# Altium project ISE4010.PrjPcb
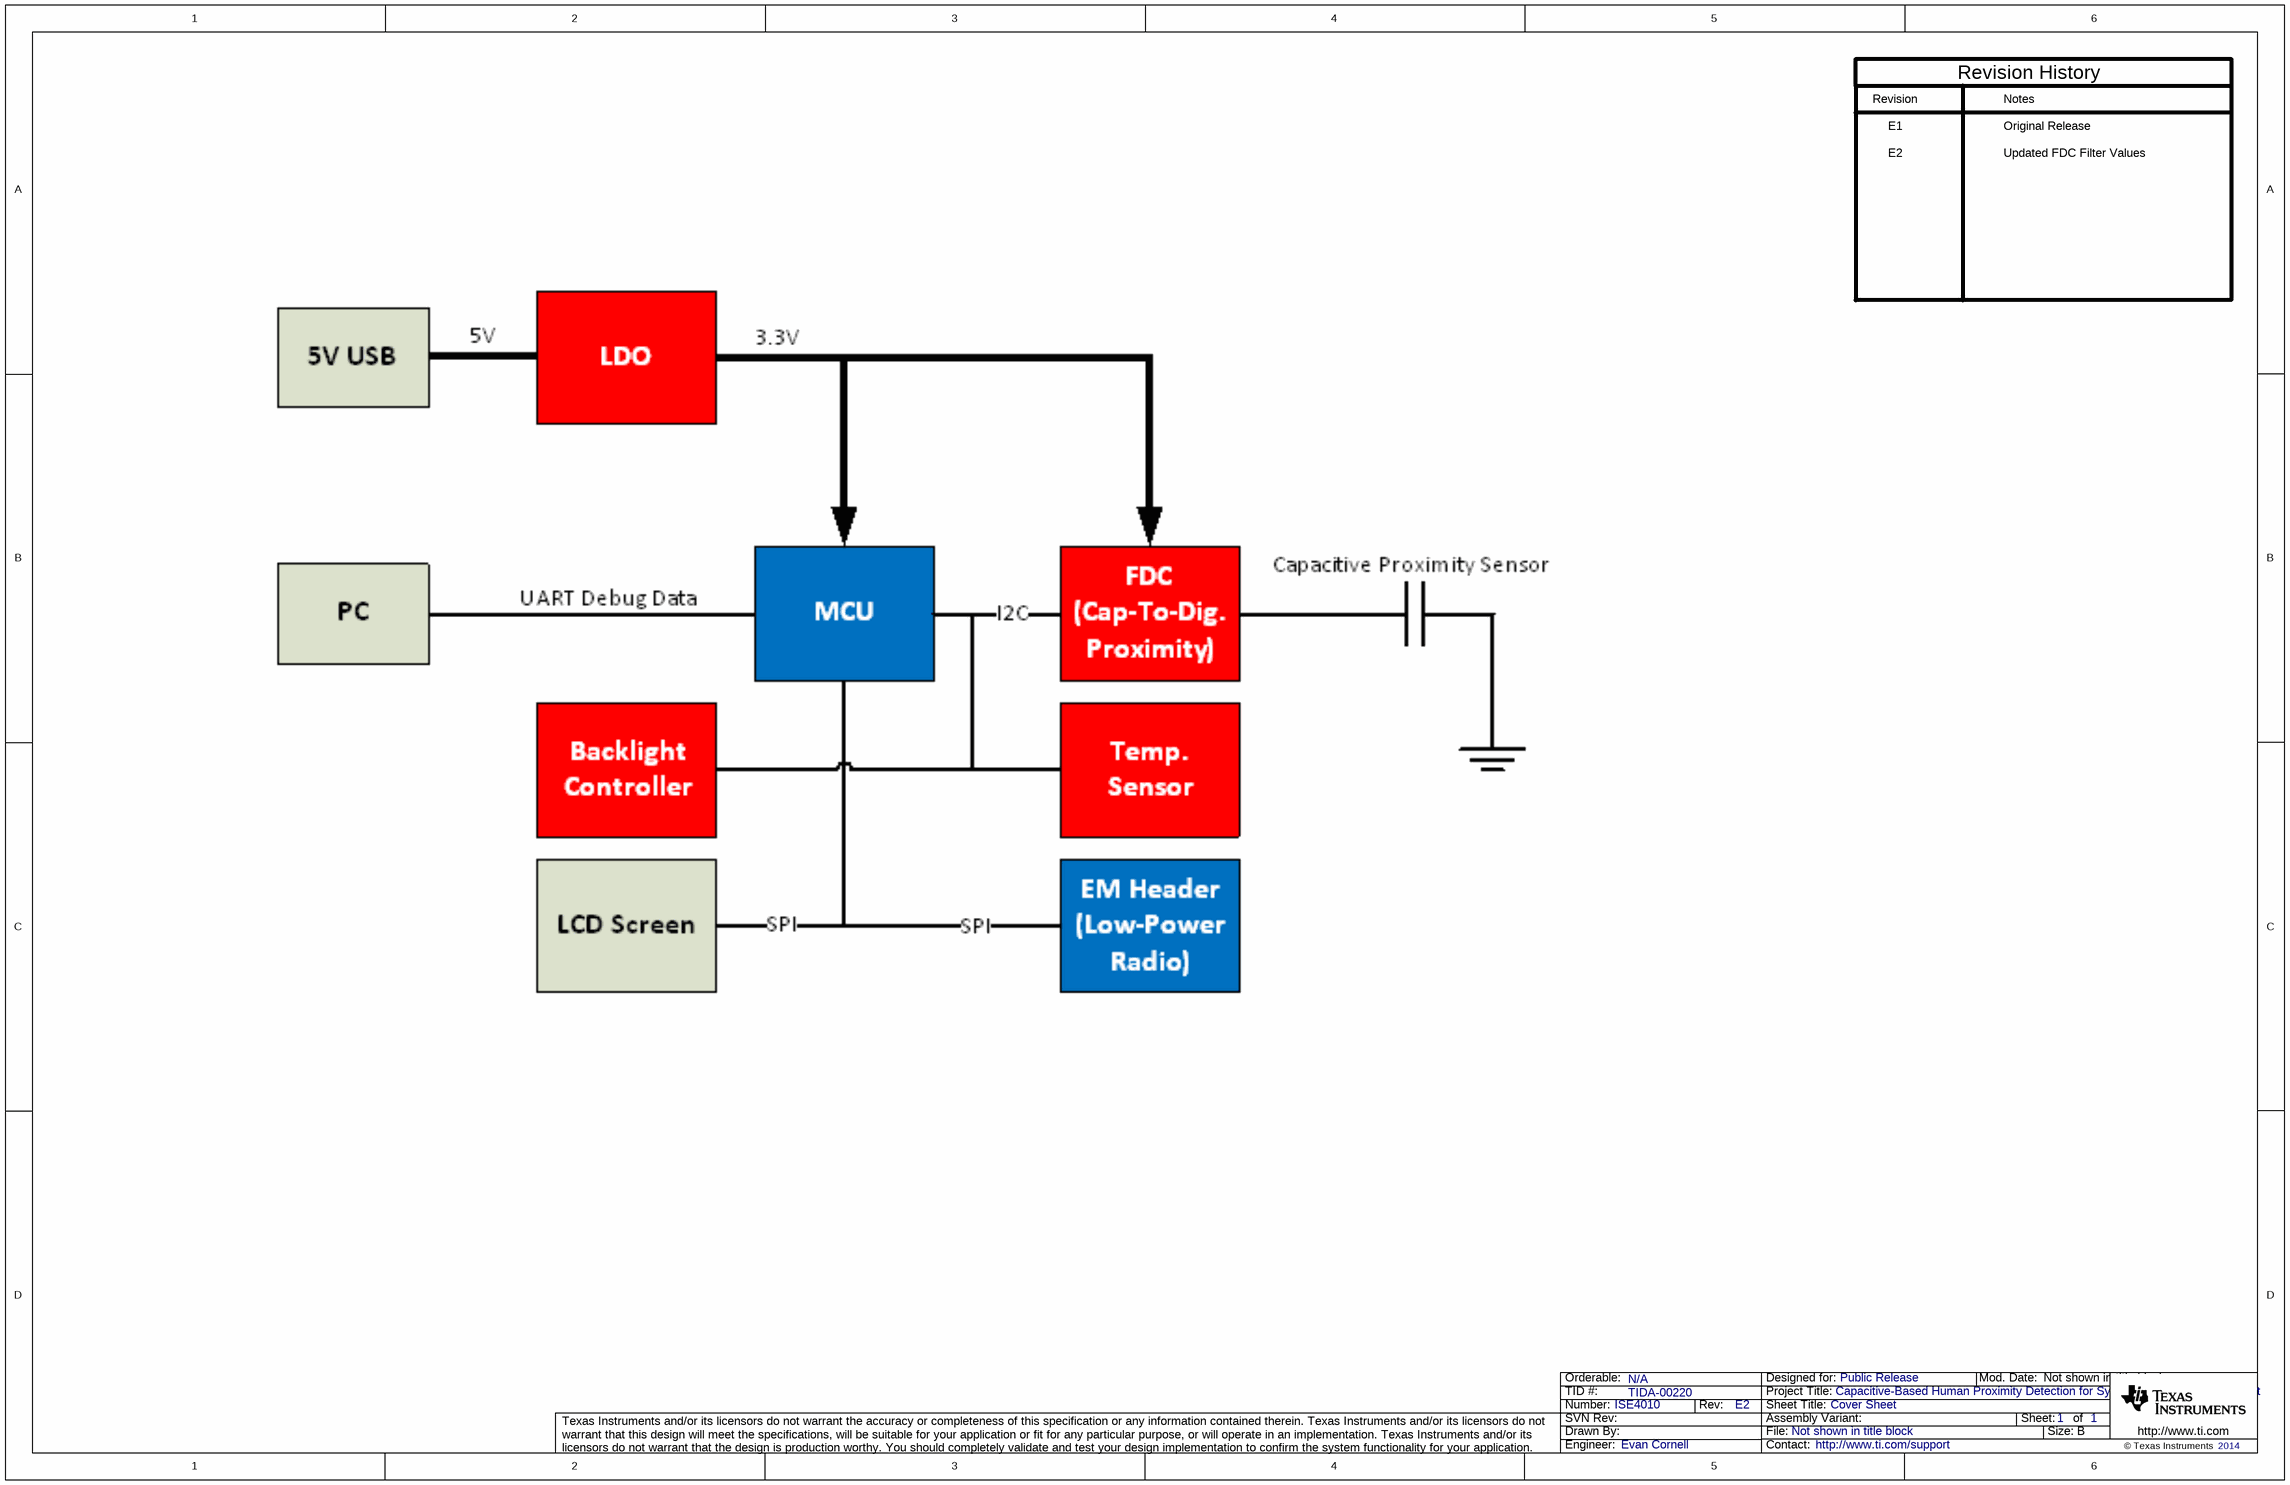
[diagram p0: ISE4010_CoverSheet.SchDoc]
CopyrightYear: 2014; EVM_orderable: N/A; PCB_Layout: Krypton Solutions /JM; PCB_Rev: E2; PRJ_Customer: Public Release; PRJ_Engineer: Evan Cornell; PRJ_Number: ISE4010; PRJ_Title: Capacitive-Based Human Proximity Detection for System Wake-Up and Interrupt; SCH_Rev: E2; TechSupport: http://www.ti.com/support; TID: TIDA-00220
4 sheets, 162 parts. Net scope: global (net labels, ports and power ports of the same name join across sheets).
Board file: ISE4010_TID.PcbDoc
Sheets:
  ISE4010_CoverSheet.SchDoc
  ISE4010_MSP430.SchDoc
  ISE4010_FDC_LCD.SchDoc
  ISE4010_TID_Hardware.SchDoc

## Sheet ISE4010_CoverSheet.SchDoc: Cover Sheet
size 431 x 279 mm; Date: Not shown in title block; ApprovedBy: Not shown in title block; CheckedBy: Not shown in title block; Author: Not shown in title block; CompanyName: Not shown in title block; Engineer: Not shown in title block; Organization: Not shown in title block; Address1: Not shown in title block; Address2: Not shown in title block; Address3: Not shown in title block; Address4: Not shown in title block; DocumentNumber: 1; Revision: Use project parameter SCH_Rev; SheetNumber: 1; SheetTotal: 1; PageSetup: Record=PageOptions¦CenterHorizontal=True¦CenterVertical=True¦PrintScale=1.00¦XCorrection=1.00¦YCorrection=1.00¦PrintKind=0¦BorderSize=5000000¦LeftOffset=0¦BottomOffset=0¦Orientation=2¦PaperLength=1000¦PaperWidth=1000¦Scale=100¦PaperSource=15¦PrintQuality=600¦MediaType=1¦DitherType=10¦PaperKind=Letter¦PrintScaleMode=1

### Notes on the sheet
- Revision
- Notes
- Revision History
- E1
- E2
- Original Release
- Updated FDC Filter Values

## Sheet ISE4010_MSP430.SchDoc: MSP430
size 431 x 279 mm; Date: Not shown in title block; ApprovedBy: Not shown in title block; CheckedBy: Not shown in title block; Author: Not shown in title block; CompanyName: Not shown in title block; DrawnBy: Evan Cornell; Engineer: Not shown in title block; Organization: Not shown in title block; Address1: Not shown in title block; Address2: Not shown in title block; Address3: Not shown in title block; Address4: Not shown in title block; DocumentNumber: 2; Revision: Use project parameter SCH_Rev; SheetNumber: 2; SheetTotal: 4; PageSetup: Record=PageOptions¦CenterHorizontal=True¦CenterVertical=True¦PrintScale=0.62¦XCorrection=1.00¦YCorrection=1.00¦PrintKind=0¦BorderSize=5000000¦LeftOffset=0¦BottomOffset=0¦Orientation=2¦PaperLength=1000¦PaperWidth=1000¦Scale=100¦PaperSource=15¦PrintQuality=600¦MediaType=1¦DitherType=10¦PaperKind=Letter¦PrintScaleMode=1
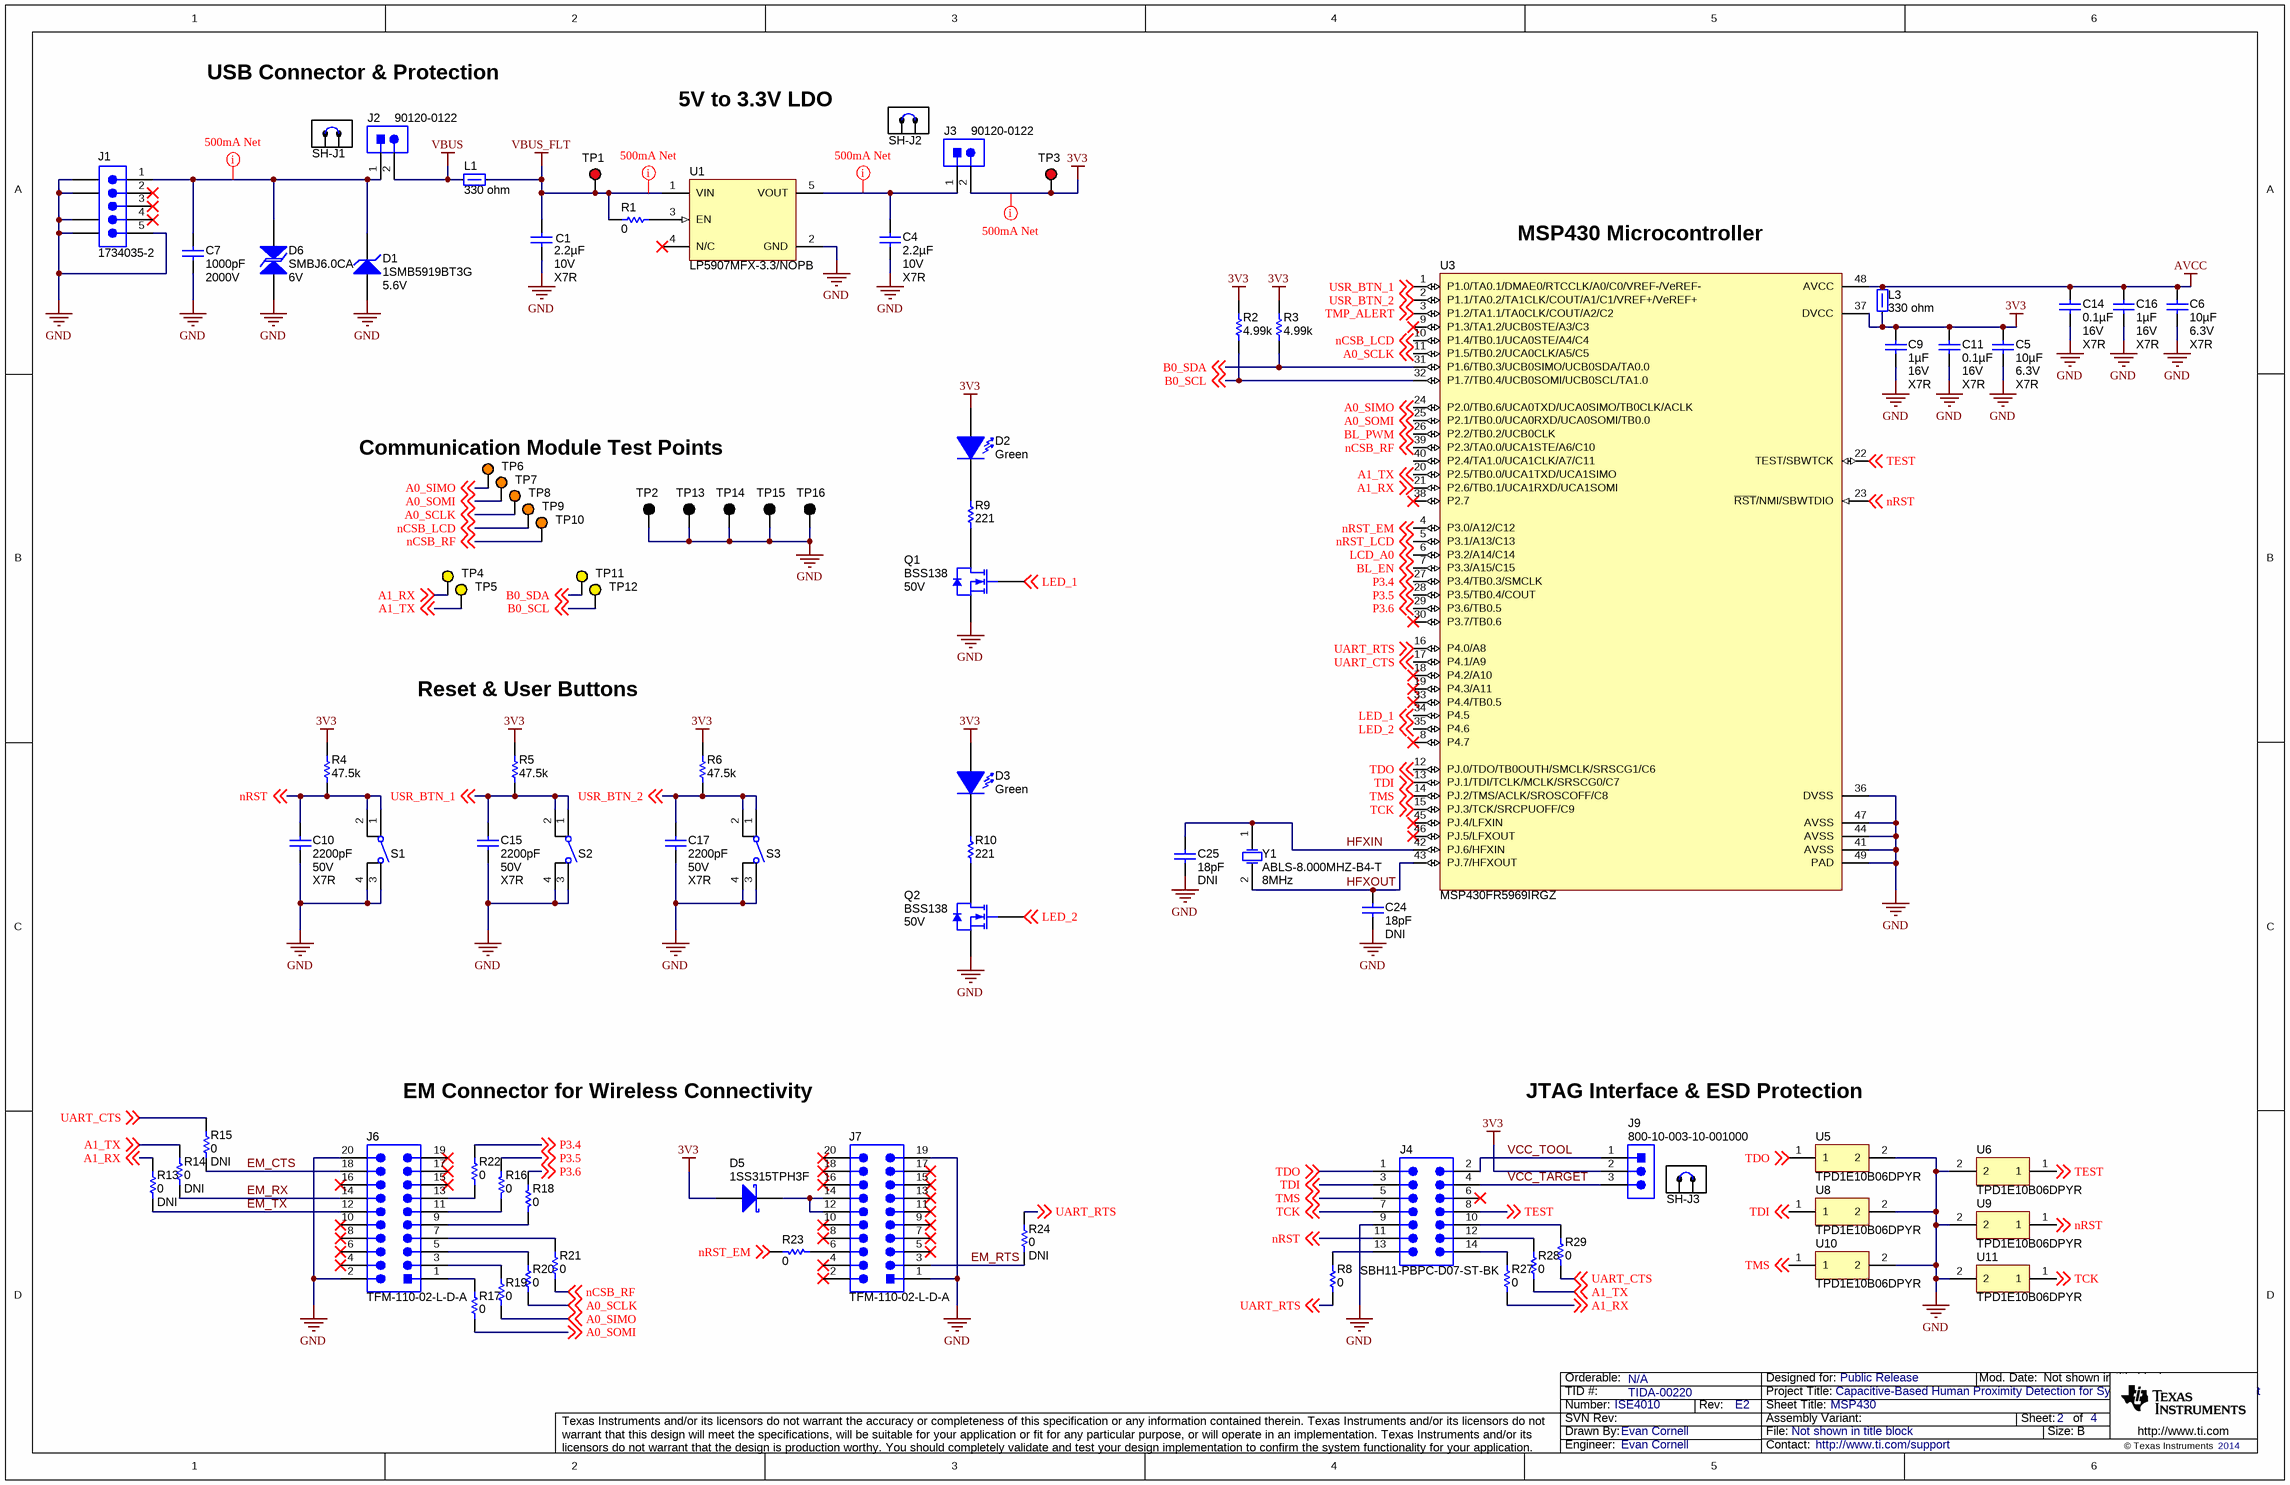
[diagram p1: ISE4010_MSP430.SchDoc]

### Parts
C1  ValueDisplayed: 2.2µF  Value2: 10V  TempCo: X7R  [0603]  (hidden comment: GRM188R71A225KE15D)
C4  ValueDisplayed: 2.2µF  Value2: 10V  TempCo: X7R  [0603]  (hidden comment: GRM188R71A225KE15D)
C5  ValueDisplayed: 10µF  Value2: 6.3V  TempCo: X7R  [0805_HV]  (hidden comment: C2012X7R0J106M125AB)
C6  ValueDisplayed: 10µF  Value2: 6.3V  TempCo: X7R  [0805_HV]  (hidden comment: C2012X7R0J106M125AB)
C7  ValueDisplayed: 1000pF  Value2: 2000V  [1210]  (hidden comment: C1210C102KGRACTU)
C9  ValueDisplayed: 1µF  Value2: 16V  TempCo: X7R  [0603]  (hidden comment: C1608X7R1C105K)
C10  ValueDisplayed: 2200pF  Value2: 50V  TempCo: X7R  [0402]  (hidden comment: C1005X7R1H222K)
C11  ValueDisplayed: 0.1µF  Value2: 16V  TempCo: X7R  [0402]  (hidden comment: GRM155R71C104KA88D)
C14  ValueDisplayed: 0.1µF  Value2: 16V  TempCo: X7R  [0402]  (hidden comment: GRM155R71C104KA88D)
C15  ValueDisplayed: 2200pF  Value2: 50V  TempCo: X7R  [0402]  (hidden comment: C1005X7R1H222K)
C16  ValueDisplayed: 1µF  Value2: 16V  TempCo: X7R  [0603]  (hidden comment: C1608X7R1C105K)
C17  ValueDisplayed: 2200pF  Value2: 50V  TempCo: X7R  [0402]  (hidden comment: C1005X7R1H222K)
C24  ValueDisplayed: 18pF  [0603]  (hidden comment: GRM1885C2A180JA01D)
C25  ValueDisplayed: 18pF  [0603]  (hidden comment: GRM1885C2A180JA01D)
D1  1SMB5919BT3G  value 5.6V  [SMB]
D2  value Green  [SML-P1_GREEN]  (hidden comment: SML-P12PTT86)
D3  value Green  [SML-P1_GREEN]  (hidden comment: SML-P12PTT86)
D5  1SS315TPH3F  [sod-323]
D6  SMBJ6.0CA  value 6V  [SMB]
J1  1734035-2  [CONN_USB-Mini-B-1734035-2]
J2  90120-0122  [CONN_90120-0122]
J3  90120-0122  [CONN_90120-0122]
J4  SBH11-PBPC-D07-ST-BK  [CONN_SBH11-PBPC-D07-ST-BK]
J6  TFM-110-02-L-D-A  [Samtec_TFM-110-02-L-D-A]
J7  TFM-110-02-L-D-A  [Samtec_TFM-110-02-L-D-A]
J9  800-10-003-10-001000  [Mill-Max_800-10-003-10-001000]
L1  value 330 ohm  [0603]  (hidden comment: BLM18SG331TN1D)
L3  value 330 ohm  [0603]  (hidden comment: BLM18SG331TN1D)
Q1  BSS138  value 50V  [SOT-23]
Q2  BSS138  value 50V  [SOT-23]
R1  value 0  [0402]  (hidden comment: CRCW04020000Z0ED)
R2  value 4.99k  [0402]  (hidden comment: CRCW04024K99FKED)
R3  value 4.99k  [0402]  (hidden comment: CRCW04024K99FKED)
R4  value 47.5k  [0603]  (hidden comment: CRCW060347K5FKEA)
R5  value 47.5k  [0603]  (hidden comment: CRCW060347K5FKEA)
R6  value 47.5k  [0603]  (hidden comment: CRCW060347K5FKEA)
R8  value 0  [0402]  (hidden comment: CRCW04020000Z0ED)
R9  value 221  [0402]  (hidden comment: CRCW0402221RFKED)
R10  value 221  [0402]  (hidden comment: CRCW0402221RFKED)
R13  value 0  [0402]  (hidden comment: CRCW04020000Z0ED)
R14  value 0  [0402]  (hidden comment: CRCW04020000Z0ED)
R15  value 0  [0402]  (hidden comment: CRCW04020000Z0ED)
R16  value 0  [0402]  (hidden comment: CRCW04020000Z0ED)
R17  value 0  [0402]  (hidden comment: CRCW04020000Z0ED)
R18  value 0  [0402]  (hidden comment: CRCW04020000Z0ED)
R19  value 0  [0402]  (hidden comment: CRCW04020000Z0ED)
R20  value 0  [0402]  (hidden comment: CRCW04020000Z0ED)
R21  value 0  [0402]  (hidden comment: CRCW04020000Z0ED)
R22  value 0  [0402]  (hidden comment: CRCW04020000Z0ED)
R23  value 0  [0402]  (hidden comment: CRCW04020000Z0ED)
R24  value 0  [0402]  (hidden comment: CRCW04020000Z0ED)
R27  value 0  [0402]  (hidden comment: CRCW04020000Z0ED)
R28  value 0  [0402]  (hidden comment: CRCW04020000Z0ED)
R29  value 0  [0402]  (hidden comment: CRCW04020000Z0ED)
S1  4-1437565-1  [SW_FSM4JSMA]  (value not drawn)
S2  4-1437565-1  [SW_FSM4JSMA]  (value not drawn)
S3  4-1437565-1  [SW_FSM4JSMA]  (value not drawn)
SH-J1  2SN-BK-G  [2SN-BK-G]  (value not drawn)
SH-J2  2SN-BK-G  [2SN-BK-G]  (value not drawn)
SH-J3  881545-2  [TE_881545-2]  (value not drawn)  (mechanical)
TP1  5000  [Keystone5000]  (value not drawn)
TP2  5001  [Keystone5001]  (value not drawn)
TP3  5000  [Keystone5000]  (value not drawn)
TP4  5004  [Keystone5004]  (value not drawn)
TP5  5004  [Keystone5004]  (value not drawn)
TP6  5003  [Keystone5003]  (value not drawn)
TP7  5003  [Keystone5003]  (value not drawn)
TP8  5003  [Keystone5003]  (value not drawn)
TP9  5003  [Keystone5003]  (value not drawn)
TP10  5003  [Keystone5003]  (value not drawn)
TP11  5004  [Keystone5004]  (value not drawn)
TP12  5004  [Keystone5004]  (value not drawn)
TP13  5001  [Keystone5001]  (value not drawn)
TP14  5001  [Keystone5001]  (value not drawn)
TP15  5001  [Keystone5001]  (value not drawn)
TP16  5001  [Keystone5001]  (value not drawn)
U1  LP5907MFX-3.3/NOPB  [DBV0005A_N]
U3  MSP430FR5969IRGZ  [RGZ0048B]
U5  TPD1E10B06DPYR  [DPY0002A]
U6  TPD1E10B06DPYR  [DPY0002A]
U8  TPD1E10B06DPYR  [DPY0002A]
U9  TPD1E10B06DPYR  [DPY0002A]
U10  TPD1E10B06DPYR  [DPY0002A]
U11  TPD1E10B06DPYR  [DPY0002A]
Y1  ABLS-8.000MHZ-B4-T  Frequency: 8MHz  [XTAL_CSM-7X]

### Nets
3V3: C5.1 C9.2 C11.2 D2.2(A) D3.2(A) D5.2(A) J3.2 J9.2 L3.1 R2.2 R3.2 R4.2 R5.2 R6.2 TP3.1 U3.37(DVCC)
AVCC: C6.1 C14.2 C16.2 L3.2 U3.48(AVCC)
GND: C1.1 C4.1 C5.2 C6.2 C7.2 C9.1 C10.2 C11.1 C14.1 C15.2 C16.1 C17.2 C24.2 C25.2 D1.2(A) D6.1 J1.5 J1.6(GND) J1.7(GND) J1.8(GND) J1.9(GND) J4.9 J6.2 J6.20 J7.1 J7.19 Q1.2(S) Q2.2(S) S1.3 S1.4 S2.3 S2.4 S3.3 S3.4 TP2.1 TP13.1 TP14.1 TP15.1 TP16.1 U1.2(GND) U3.36(DVSS) U3.41(AVSS) U3.44(AVSS) U3.47(AVSS) U3.49(PAD) U5.2 U6.2 U8.2 U9.2 U10.2 U11.2
VBUS: J2.2 L1.1
VBUS_FLT: C1.2 L1.2 R1.2 TP1.1 U1.1(VIN)
A0_SCLK: R20.2 TP8.1 U3.11(P1.5/TB0.2/UCA0CLK/A5/C5) ; off-sheet A0_SCLK
A0_SIMO: R19.2 TP6.1 U3.24(P2.0/TB0.6/UCA0TXD/UCA0SIMO/TB0CLK/ACLK) ; off-sheet A0_SIMO
A0_SOMI: R17.1 TP7.1 U3.25(P2.1/TB0.0/UCA0RXD/UCA0SOMI/TB0.0) ; off-sheet A0_SOMI
A1_RX: R13.1 R27.1 TP4.1 U3.21(P2.6/TB0.1/UCA1RXD/UCA1SOMI) ; off-sheet A1_RX
A1_TX: R14.1 R28.1 TP5.1 U3.20(P2.5/TB0.0/UCA1TXD/UCA1SIMO) ; off-sheet A1_TX
B0_SCL: R2.1 TP12.1 U3.32(P1.7/TB0.4/UCB0SOMI/UCB0SCL/TA1.0) ; off-sheet B0_SCL
B0_SDA: R3.1 TP11.1 U3.31(P1.6/TB0.3/UCB0SIMO/UCB0SDA/TA0.0) ; off-sheet B0_SDA
BL_EN: U3.7(P3.3/A15/C15) ; off-sheet BL_EN
BL_PWM: U3.26(P2.2/TB0.2/UCB0CLK) ; off-sheet BL_PWM
EM_CTS: J6.18 R15.1
EM_RTS: J7.3 R24.2
EM_RX: J6.14 R14.2
EM_TX: J6.12 R13.2
HFXIN: C25.1 U3.42(PJ.6/HFXIN) Y1.1(OSC1)
HFXOUT: C24.1 U3.43(PJ.7/HFXOUT) Y1.2(OSC2)
LCD_A0: U3.6(P3.2/A14/C14) ; off-sheet LCD_A0
LED_1: Q1.1(G) U3.34(P4.5) ; off-sheet LED_1
LED_2: Q2.1(G) U3.35(P4.6) ; off-sheet LED_2
nCSB_LCD: TP9.1 U3.10(P1.4/TB0.1/UCA0STE/A4/C4) ; off-sheet nCSB_LCD
nCSB_RF: R21.2 TP10.1 U3.39(P2.3/TA0.0/UCA1STE/A6/C10) ; off-sheet nCSB_RF
nRST: C10.1 J4.11 R4.1 S1.1 S1.2 U3.23(~{RST}/NMI/SBWTDIO) U9.1 ; off-sheet nRST
nRST_EM: R23.2 U3.4(P3.0/A12/C12) ; off-sheet nRST_EM
nRST_LCD: U3.5(P3.1/A13/C13) ; off-sheet nRST_LCD
P3.4: R22.2 U3.27(P3.4/TB0.3/SMCLK) ; off-sheet P3.4
P3.5: R16.1 U3.28(P3.5/TB0.4/COUT) ; off-sheet P3.5
P3.6: R18.1 U3.29(P3.6/TB0.5) ; off-sheet P3.6
TCK: J4.7 U3.15(PJ.3/TCK/SRCPUOFF/C9) U11.1 ; off-sheet TCK
TDI: J4.3 U3.13(PJ.1/TDI/TCLK/MCLK/SRSCG0/C7) U8.1 ; off-sheet TDI
TDO: J4.1 U3.12(PJ.0/TDO/TB0OUTH/SMCLK/SRSCG1/C6) U5.1 ; off-sheet TDO
TEST: J4.8 U3.22(TEST/SBWTCK) U6.1 ; off-sheet TEST
TMP_ALERT: U3.3(P1.2/TA1.1/TA0CLK/COUT/A2/C2) ; off-sheet TMP_ALERT
TMS: J4.5 U3.14(PJ.2/TMS/ACLK/SROSCOFF/C8) U10.1 ; off-sheet TMS
UART_CTS: R15.2 R29.1 U3.17(P4.1/A9) ; off-sheet UART_CTS
UART_RTS: R8.1 R24.1 U3.16(P4.0/A8) ; off-sheet UART_RTS
USR_BTN_1: C15.1 R5.1 S2.1 S2.2 U3.1(P1.0/TA0.1/DMAE0/RTCCLK/A0/C0/VREF-/VeREF-) ; off-sheet USR_BTN_1
USR_BTN_2: C17.1 R6.1 S3.1 S3.2 U3.2(P1.1/TA0.2/TA1CLK/COUT/A1/C1/VREF+/VeREF+) ; off-sheet USR_BTN_2
VCC_TARGET: J4.4 J9.3
VCC_TOOL: J4.2 J9.1
NetC4_2: C4.2 J3.1 U1.5(VOUT)
NetC7_1: C7.1 D1.1(K) D6.2 J1.1 J2.1
NetD2_1: D2.1(K) R9.2
NetD3_1: D3.1(K) R10.2
NetD5_1: D5.1(K) J7.12 J7.14
NetJ4_10: J4.10 R29.2
NetJ4_12: J4.12 R28.2
NetJ4_13: J4.13 R8.2
NetJ4_14: J4.14 R27.2
NetJ6_1: J6.1 R17.2
NetJ6_3: J6.3 R19.1
NetJ6_5: J6.5 R20.1
NetJ6_7: J6.7 R21.1
NetJ6_9: J6.9 R18.2
NetJ6_11: J6.11 R16.2
NetJ6_13: J6.13 R22.1
NetJ7_6: J7.6 R23.1
NetQ1_3: Q1.3(D) R9.1
NetQ2_3: Q2.3(D) R10.1
NetR1_1: R1.1 U1.3(EN)

Not connected (* = marked no-connect by the designer): J1 2* 3* 4*; J4 6*; J6 4* 6* 8* 10* 15* 16* 17* 19*; J7 2* 4* 5* 7* 8* 9* 10* 11* 13* 15* 16* 17* 18* 20*; U1 4(N/C)*; U3 8(P4.7)* 9(P1.3/TA1.2/UCB0STE/A3/C3)* 18(P4.2/A10)* 19(P4.3/A11)* 30(P3.7/TB0.6)* 33(P4.4/TB0.5)* 38(P2.7)* 40(P2.4/TA1.0/UCA1CLK/A7/C11) 45(PJ.4/LFXIN)* 46(PJ.5/LFXOUT)*

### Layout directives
rule Width Constraint [Pref Width = 25mil    Min Width = 5mil    Max Width = 100mil]: 3V3, NetC4_2, NetC7_1, VBUS_FLT

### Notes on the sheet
- USB Connector & Protection
- 5V to 3.3V LDO
- (near U3) MSP430 Microcontroller
- (near TP6) Communication Module Test Points
- Reset & User Buttons
- EM Connector for Wireless Connectivity
- JTAG Interface & ESD Protection

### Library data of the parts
C1 = GRM188R71A225KE15D: CAP, CERM, 2.2uF, 10V, +/-10%, X7R, 0603; Manufacturer: MuRata; Polarized: N; CompType: Capacitor; U/M: EA; Cap_F: 0.0000022; Tolerance_%: 10; ESR_Ohm: 0.009; Value1: 0.009 ohm; TaMin_C: -55; TaMax_C: 125
C4 = GRM188R71A225KE15D: CAP, CERM, 2.2 µF, 10 V, +/- 10%, X7R, 0603; Manufacturer: MuRata; Polarized: N; CompType: Capacitor; Value: 2.2uF; U/M: EA; Cap_F: 0.0000022; Tolerance_%: 10; ESR_ohm: 0.009; Value1: 0.009 ohm; TaMin_C: -55; TaMax_C: 125
C5 C6 = C2012X7R0J106M125AB: CAP, CERM, 10 µF, 6.3 V, +/- 20%, X7R, 0805; Manufacturer: TDK; Polarized: N; CompType: Capacitor; Value: 10uF; U/M: EA; Cap_F: 0.00001; Tolerance_%: 20; Value1: Unknown; VDC_V: 6.3; TaMin_C: -55; TaMax_C: 125; Cap_Case: 0805
C7 = C1210C102KGRACTU: CAP, CERM, 1000pF, 2000V, +/-10%, X7R, 1210; Manufacturer: Kemet; Polarized: N; CompType: Capacitor; U/M: EA; Cap_F: 0.000000001; Tolerance_%: 10; Value1: Unknown; VDC_V: 2000; TaMin_C: -55; TaMax_C: 125
C9 C16 = C1608X7R1C105K: CAP, CERM, 1uF, 16V, +/-10%, X7R, 0603; Manufacturer: TDK; Polarized: N; CompType: Capacitor; U/M: EA; Cap_F: 0.000001; Tolerance_%: 10; ESR_Ohm: 0.0057; Value1: 0.0057 ohm; VDC_V: 16; TaMin_C: -55; TaMax_C: 125
C10 C15 C17 = C1005X7R1H222K: CAP, CERM, 2200pF, 50V, +/-10%, X7R, 0402; Manufacturer: TDK; Polarized: N; CompType: Capacitor; U/M: EA; Cap_F: 0.0000000022; Tolerance_%: 10; ESR_Ohm: 0.1433; Value1: 0.1433 ohm; VDC_V: 50; TaMin_C: -55; TaMax_C: 125
C11 C14 = GRM155R71C104KA88D: CAP, CERM, 0.1uF, 16V, +/-10%, X7R, 0402; Manufacturer: MuRata; Polarized: N; CompType: Capacitor; U/M: EA; Cap_F: 0.0000001; Tolerance_%: 10; Value1: Unknown; VDC_V: 16; TaMin_C: -55; TaMax_C: 125
C24 C25 = GRM1885C2A180JA01D: CAP, CERM, 18pF, 100V, +/-5%, C0G/NP0, 0603; Manufacturer: MuRata; Polarized: N; CompType: Capacitor; U/M: EA; Cap_F: 0.000000000018; Tolerance_%: 5; Value1: Unknown; VDC_V: 100; TaMin_C: -55; TaMax_C: 125
D1 = 1SMB5919BT3G: Diode, Zener, 5.6V, 550 mW, SMB; Manufacturer: ON Semiconductor; U/M: EA; Power_W: 0.55; Vz_V: 5.6; Value1: 0.55W; RJA_CperW: 226; SymbolCreator: a0412235
D2 D3 = SML-P12PTT86: LED, Green, SMD; Manufacturer: Rohm; Type: AlInGaP; Vf_V: 2.2; Value2: 2.2V; Io_A: 0.02; Value1: W; U/M: EA
D5 = 1SS315TPH3F: Diode, Schottky, 5V, 0.03A, SOD-323; Manufacturer: Toshiba; U/M: EA; Vf_V: 0.38; Value2: 0.38V; Io_A: 0.03; Vr_V: 5; TJmax_C: 125
D6 = SMBJ6.0CA: Diode, TVS, Bi, 6 V, 600 W, SMB; Manufacturer: Littelfuse; U/M: EA; Power_W: 600; Vr_V: 6; Value1: 600W; RJA_CperW: 100
J1 = 1734035-2: Connector, Receptacle, Mini-USB Type B, R/A, Top Mount SMT; Manufacturer: TE Connectivity; SymbolCreator: A0412235; U/M: EA
J2 = 90120-0122: Header, 100mil, 2x1, Tin plated, TH; Manufacturer: Molex; SymbolCreator: a0412235; U/M: EA
J3 = 90120-0122: Header, 100mil, 2x1, Tin, TH; Manufacturer: Molex; SymbolCreator: a0412235; U/M: EA
J4 = SBH11-PBPC-D07-ST-BK: Header (shrouded), 100 mil, 7x2, Gold plated, TH; Manufacturer: Sullins Connector Solutions; SymbolCreator: a0412235; CompType: Connector; U/M: EA
J6 J7 = TFM-110-02-L-D-A: Straight Low Profile Header, 10x2 Position,1.27 mm Pitch, SMT; Manufacturer: Samtec; SymbolCreator: a0412235; U/M: EA
J9 = 800-10-003-10-001000: Header, 3x1, 100mil, SMT; Manufacturer: Mill-Max; SymbolCreator: a0799628; U/M: EA
L1 L3 = BLM18SG331TN1D: 1.5A Ferrite Bead, 330 ohm @ 100MHz, SMD; Manufacturer: MuRata; Imax_A: 1.5; DCR_ohm: 0.07; Value1: 0.07 ohm; ZTyp@100MHz_Ohm: 330; U/M: EA
Q1 Q2 = BSS138: MOSFET, N-CH, 50V, 0.22A, SOT-23; Manufacturer: Fairchild Semiconductor; Alternate Manufacturer: None; U/M: EA; ChType: N; VdsMax_V: 50; Value1: 6 ohm; Rdson45_Ohm: 6; Value2: 1.7 nC; QgTyp_nC: 1.7; Vgs_V: 20; IdsMax_A: 0.22
R1 R8 R13-R24 R27-R29 = CRCW04020000Z0ED: RES, 0 ohm, 5%, 0.063W, 0402; Manufacturer: Vishay-Dale; CompType: Resistor; Value_Code: 0000; Tolerance_%: 5; Power_W: 0.063; VDC_V: 50; TempCo: 200 ppm/C; EIA_Code: E24; U/M: EA
R2 R3 = CRCW04024K99FKED: RES, 4.99k ohm, 1%, 0.063W, 0402; Manufacturer: Vishay-Dale; CompType: Resistor; Res_ohm: 4990; Value_Code: 4k99; Tolerance_%: 1; Power_W: 0.063; VDC_V: 50; TempCo: 100 ppm/C; EIA_Code: E96; U/M: EA
R4-R6 = CRCW060347K5FKEA: RES, 47.5k ohm, 1%, 0.1W, 0603; Manufacturer: Vishay-Dale; CompType: Resistor; Res_ohm: 47500; Value_Code: 47k5; Tolerance_%: 1; Power_W: 0.1; VDC_V: 75; TempCo: 100 ppm/C; EIA_Code: E96; U/M: EA
R9 R10 = CRCW0402221RFKED: RES, 221 ohm, 1%, 0.063W, 0402; Manufacturer: Vishay-Dale; CompType: Resistor; Value_Code: 221R; Tolerance_%: 1; Power_W: 0.063; VDC_V: 50; TempCo: 100 ppm/C; EIA_Code: E96; U/M: EA
S1-S3 = 4-1437565-1: Switch, Tactile, SPST-NO, 0.05A, 12V, SMT; Manufacturer: TE Connectivity; SymbolCreator: a0412235; VDC_V: 12; SwitchFunction: Off-Mom; PositionCount: 1; CurrentRating_mA: 50
SH-J1 SH-J2 = 2SN-BK-G: Shunt, 2mm, Gold plated, Black; Manufacturer: Samtec; Value: 1x2; Note: You can "mate" this to a header by matching the designator.  i.e. use SH-J3 for header J3
SH-J3 = 881545-2: Shunt, 100mil, Gold plated, Black; Manufacturer: TE Connectivity
TP1 TP3 = 5000: Test Point, Miniature, Red, TH; Manufacturer: Keystone; CompType: Test Point Loop; U/M: EA
TP2 TP13-TP16 = 5001: Test Point, Miniature, Black, TH; Manufacturer: Keystone; CompType: Test Point Loop; U/M: EA
TP4 TP5 TP11 TP12 = 5004: Test Point, Miniature, Yellow, TH; Manufacturer: Keystone; CompType: Test Point Loop; U/M: EA
TP6-TP10 = 5003: Test Point, Miniature, Orange, TH; Manufacturer: Keystone; CompType: Test Point Loop; U/M: EA
U1 = LP5907MFX-3.3/NOPB: ULTRA LOW-NOISE, 250-mA LINEAR REGULATOR FOR RF AND ANALOG CIRCUITS REQUIRES NO BYPASS CAPACITOR, DBV0005A; Manufacturer: Texas Instruments; Alternate Manufacturer: None; CompType: IC; SymbolCreator: a0799628; U/M: EA
U3 = MSP430FR5969IRGZ: Mixed Signal Microcontroller, RGZ0048B; Alternate Manufacturer: None; Manufacturer: Texas Instruments; SymbolCreator: a0411947; CompType: IC; U/M: EA
U5 U6 U8-U11 = TPD1E10B06DPYR: ESD in 0402 Package with 10 pF Capacitance and 6 V Breakdown, 1 Channel, -40 to +125 degC, 2-pin X2SON (DPY), Green (RoHS & no Sb/Br); Manufacturer: Texas Instruments; Alternate Manufacturer: None; Alternate PartNumber: Equivalent; Breakdown Voltage(Min)(V): 6; Eco-Plan: TBD; IEC 61000-4-2 Air-Gap(+/- kV): 30; IO Capacitance(Typ)(pF): 10; SubFamily: ESD Solution
Y1 = ABLS-8.000MHZ-B4-T: Crystal, 8MHz, 18pF, SMD; Manufacturer: Abracon Corportation; SymbolCreator: a0412235; U/M: EA; TaMin_C: 0; TaMax_C: 70; Frequency Stability: ±50ppm

## Sheet ISE4010_FDC_LCD.SchDoc: FDC & LCD
size 431 x 279 mm; Date: Not shown in title block; ApprovedBy: Not shown in title block; CheckedBy: Not shown in title block; Author: Not shown in title block; CompanyName: Not shown in title block; Engineer: Not shown in title block; Organization: Not shown in title block; Address1: Not shown in title block; Address2: Not shown in title block; Address3: Not shown in title block; Address4: Not shown in title block; DocumentNumber: 1; Revision: Use project parameter SCH_Rev; SheetNumber: 1; SheetTotal: 1; PageSetup: Record=PageOptions¦CenterHorizontal=True¦CenterVertical=True¦PrintScale=1.00¦XCorrection=1.00¦YCorrection=1.00¦PrintKind=0¦BorderSize=5000000¦LeftOffset=0¦BottomOffset=0¦Orientation=2¦PaperLength=1000¦PaperWidth=1000¦Scale=100¦PaperSource=15¦PrintQuality=600¦MediaType=1¦DitherType=10¦PaperKind=Letter¦PrintScaleMode=1
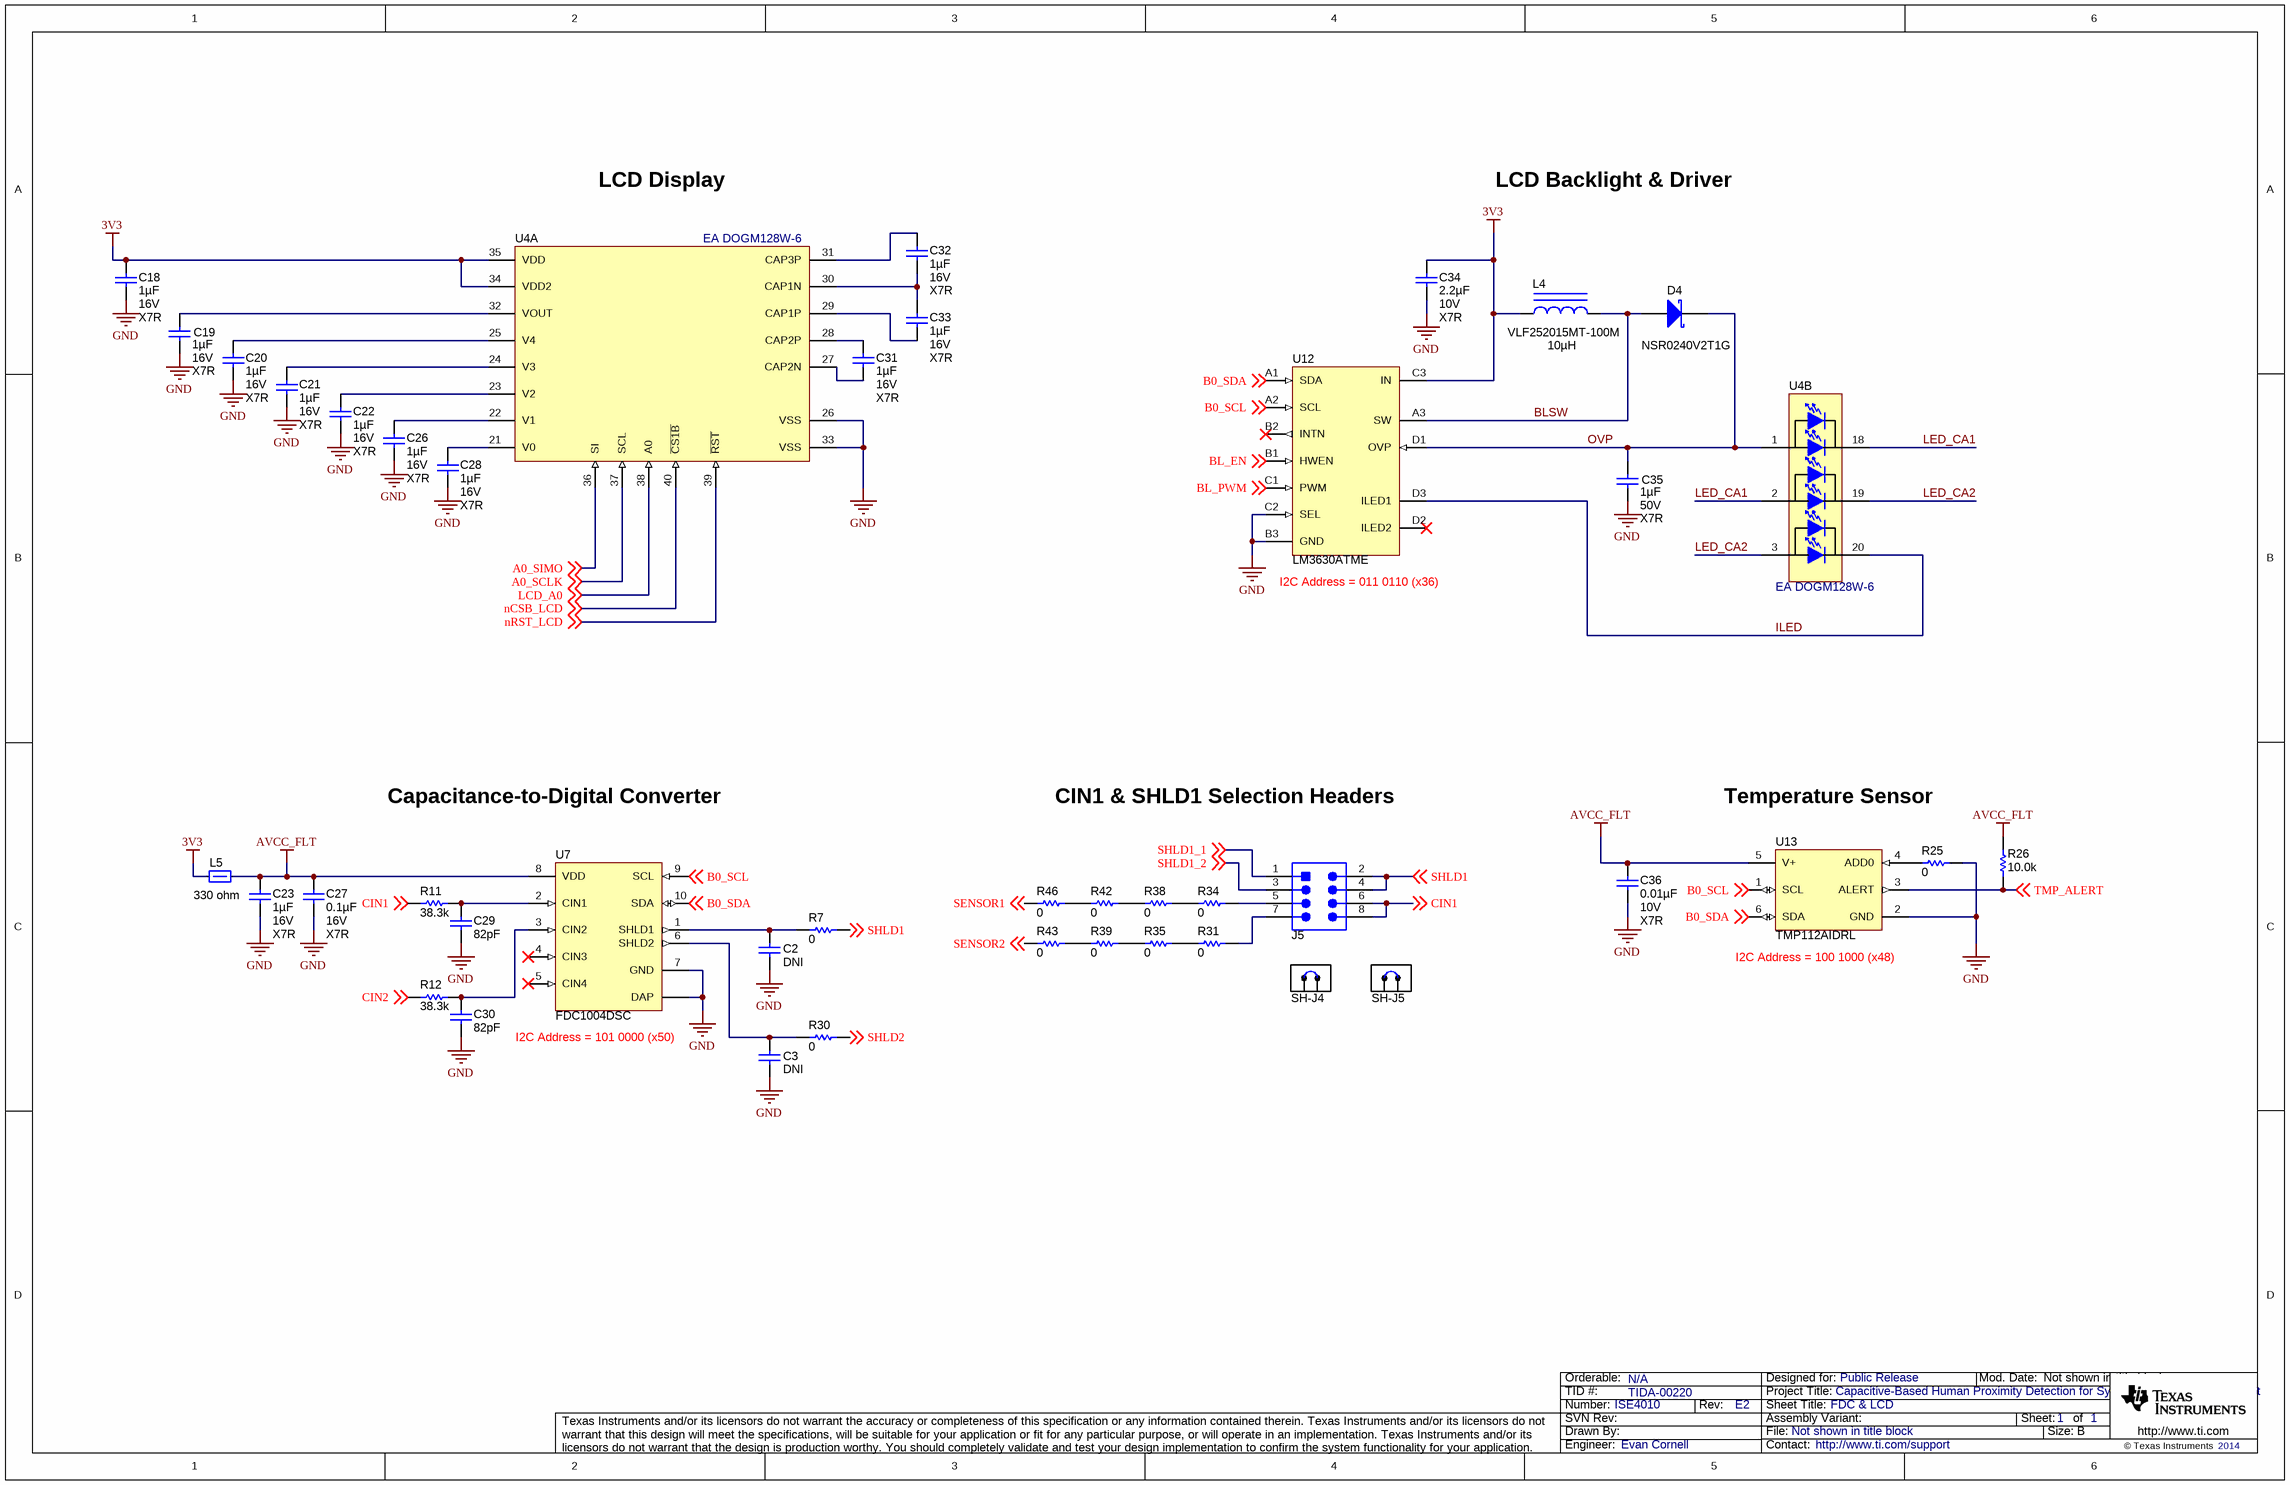
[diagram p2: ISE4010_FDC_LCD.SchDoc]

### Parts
C2  Used in BOM report  [0402]  (value not drawn)
C3  Used in BOM report  [0402]  (value not drawn)
C18  ValueDisplayed: 1µF  Value2: 16V  TempCo: X7R  [0603]  (hidden comment: C1608X7R1C105K)
C19  ValueDisplayed: 1µF  Value2: 16V  TempCo: X7R  [0603]  (hidden comment: C1608X7R1C105K)
C20  ValueDisplayed: 1µF  Value2: 16V  TempCo: X7R  [0603]  (hidden comment: C1608X7R1C105K)
C21  ValueDisplayed: 1µF  Value2: 16V  TempCo: X7R  [0603]  (hidden comment: C1608X7R1C105K)
C22  ValueDisplayed: 1µF  Value2: 16V  TempCo: X7R  [0603]  (hidden comment: C1608X7R1C105K)
C23  ValueDisplayed: 1µF  Value2: 16V  TempCo: X7R  [0603]  (hidden comment: C1608X7R1C105K)
C26  ValueDisplayed: 1µF  Value2: 16V  TempCo: X7R  [0603]  (hidden comment: C1608X7R1C105K)
C27  ValueDisplayed: 0.1µF  Value2: 16V  TempCo: X7R  [0402]  (hidden comment: GRM155R71C104KA88D)
C28  ValueDisplayed: 1µF  Value2: 16V  TempCo: X7R  [0603]  (hidden comment: C1608X7R1C105K)
C29  ValueDisplayed: 82pF  [0402]  (hidden comment: GRM1555C1H820JA01D)
C30  ValueDisplayed: 82pF  [0402]  (hidden comment: GRM1555C1H820JA01D)
C31  ValueDisplayed: 1µF  Value2: 16V  TempCo: X7R  [0603]  (hidden comment: C1608X7R1C105K)
C32  ValueDisplayed: 1µF  Value2: 16V  TempCo: X7R  [0603]  (hidden comment: C1608X7R1C105K)
C33  ValueDisplayed: 1µF  Value2: 16V  TempCo: X7R  [0603]  (hidden comment: C1608X7R1C105K)
C34  ValueDisplayed: 2.2µF  Value2: 10V  TempCo: X7R  [0603]  (hidden comment: GRM188R71A225KE15D)
C35  ValueDisplayed: 1µF  Value2: 50V  TempCo: X7R  [0603]  (hidden comment: UMK107AB7105KA-T)
C36  ValueDisplayed: 0.01µF  Value2: 10V  TempCo: X7R  [0201]  (hidden comment: GRM033R71A103KA01D)
D4  NSR0240V2T1G  [SOD-523]
J5  TSW-104-07-G-D  [TSW-104-07-G-D]  (value not drawn)
L4  VLF252015MT-100M  ValueDisplayed: 10µH  [IND_VLF252015]
L5  value 330 ohm  [0603]  (hidden comment: BLM18SG331TN1D)
R7  ValueDisplayed: 0  [0402]  (hidden comment: CRCW04020000Z0ED)
R11  ValueDisplayed: 38.3k  [0402]  (hidden comment: CRCW040238K3FKED)
R12  ValueDisplayed: 38.3k  [0402]  (hidden comment: CRCW040238K3FKED)
R25  value 0  [0402]  (hidden comment: CRCW04020000Z0ED)
R26  value 10.0k  [0402]  (hidden comment: CRCW040210K0FKED)
R30  ValueDisplayed: 0  [0402]  (hidden comment: CRCW04020000Z0ED)
R31  value 0  [2512]  (hidden comment: CRCW25120000Z0EG)
R34  value 0  [2512]  (hidden comment: CRCW25120000Z0EG)
R35  value 0  [2512]  (hidden comment: CRCW25120000Z0EG)
R38  value 0  [2512]  (hidden comment: CRCW25120000Z0EG)
R39  value 0  [2512]  (hidden comment: CRCW25120000Z0EG)
R42  value 0  [2512]  (hidden comment: CRCW25120000Z0EG)
R43  value 0  [2512]  (hidden comment: CRCW25120000Z0EG)
R46  value 0  [2512]  (hidden comment: CRCW25120000Z0EG)
SH-J4  2SN-BK-G  [2SN-BK-G]  (value not drawn)
SH-J5  2SN-BK-G  [2SN-BK-G]  (value not drawn)
U4  EA DOGM128W-6  [LCD-MODULE_EA DOGM128W-6]  (parts A,B of 2)
U7  FDC1004DSC  [DSC0010B]
U12  LM3630ATME  [YFQ0012AKAR]
U13  TMP112AIDRL  [DRL0006A]

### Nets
3V3: C18.1 C34.1 L4.1 L5.1 U4.34(VDD2) U4.35(VDD) U12.C3(IN)
AVCC_FLT: C23.1 C27.2 C36.1 L5.2 R26.2 U7.8(VDD) U13.5(V+)
GND: C2.2 C3.2 C18.2 C19.2 C20.2 C21.2 C22.2 C23.2 C26.2 C27.1 C28.2 C29.1 C30.1 C34.2 C35.2 C36.2 R25.2 U4.26(VSS) U4.33(VSS) U7.7(GND) U7.11(DAP) U12.B3(GND) U12.C2(SEL) U13.2(GND)
A0_SCLK: U4.37(SCL) ; off-sheet A0_SCLK
A0_SIMO: U4.36(SI) ; off-sheet A0_SIMO
B0_SCL: U7.9(SCL) U12.A2(SCL) U13.1(SCL) ; off-sheet B0_SCL
B0_SDA: U7.10(SDA) U12.A1(SDA) U13.6(SDA) ; off-sheet B0_SDA
BL_EN: U12.B1(HWEN) ; off-sheet BL_EN
BL_PWM: U12.C1(PWM) ; off-sheet BL_PWM
BLSW: D4.2(A) L4.2 U12.A3(SW)
CIN1: J5.6 J5.8 R11.1 ; off-sheet CIN1
CIN2: R12.1 ; off-sheet CIN2
ILED: U4.20(K) U12.D3(ILED1)
LCD_A0: U4.38(A0) ; off-sheet LCD_A0
LED_CA1: U4.2(A) U4.18(K)
LED_CA2: U4.3(A) U4.19(K)
nCSB_LCD: U4.40(~{CS1B}) ; off-sheet nCSB_LCD
nRST_LCD: U4.39(~{RST}) ; off-sheet nRST_LCD
OVP: C35.1 D4.1(K) U4.1(A) U12.D1(OVP)
SENSOR1: R46.2 ; off-sheet SENSOR1
SENSOR2: R43.2 ; off-sheet SENSOR2
SHLD1: J5.2 J5.4 R7.2 ; off-sheet SHLD1
SHLD1_1: J5.1 ; off-sheet SHLD1_1
SHLD1_2: J5.3 ; off-sheet SHLD1_2
SHLD2: R30.2 ; off-sheet SHLD2
TMP_ALERT: R26.1 U13.3(ALERT) ; off-sheet TMP_ALERT
NetC2_1: C2.1 R7.1 U7.1(SHLD1)
NetC3_1: C3.1 R30.1 U7.6(SHLD2)
NetC19_1: C19.1 U4.32(VOUT)
NetC20_1: C20.1 U4.25(V4)
NetC21_1: C21.1 U4.24(V3)
NetC22_1: C22.1 U4.23(V2)
NetC26_1: C26.1 U4.22(V1)
NetC28_1: C28.1 U4.21(V0)
NetC29_2: C29.2 R11.2 U7.2(CIN1)
NetC30_2: C30.2 R12.2 U7.3(CIN2)
NetC31_1: C31.1 U4.28(CAP2P)
NetC31_2: C31.2 U4.27(CAP2N)
NetC32_1: C32.1 U4.31(CAP3P)
NetC32_2: C32.2 C33.1 U4.30(CAP1N)
NetC33_2: C33.2 U4.29(CAP1P)
NetJ5_5: J5.5 R34.1
NetJ5_7: J5.7 R31.1
NetR25_1: R25.1 U13.4(ADD0)
NetR31_2: R31.2 R35.1
NetR34_2: R34.2 R38.1
NetR35_2: R35.2 R39.1
NetR38_2: R38.2 R42.1
NetR39_2: R39.2 R43.1
NetR42_2: R42.2 R46.1

Not connected (* = marked no-connect by the designer): U7 4(CIN3)* 5(CIN4)*; U12 B2(INTN)* D2(ILED2)*

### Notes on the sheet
- LCD Display
- LCD Backlight & Driver
- (near U12) I2C Address = 011 0110 (x36)
- Capacitance-to-Digital Converter
- CIN1 & SHLD1 Selection Headers
- Temperature Sensor
- (near U13) I2C Address = 100 1000 (x48)
- I2C Address = 101 0000 (x50)

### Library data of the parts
C2 C3 = Capacitor: CAP, CERM, xxxF, xxV, [TempCo], xx%, [PackageReference]; Polarized: N; U/M: EA
C18-C23 C26 C28 C31-C33 = C1608X7R1C105K: as C9 on sheet ISE4010_MSP430
C27 = GRM155R71C104KA88D: as C11 on sheet ISE4010_MSP430
C29 C30 = GRM1555C1H820JA01D: CAP, CERM, 82 pF, 50 V, +/- 5%, C0G/NP0, 0402; Manufacturer: MuRata; Polarized: N; CompType: Capacitor; Value: 82pF; U/M: EA; Cap_F: 0.000000000082; Tolerance_%: 5; Value1: Unknown; VDC_V: 50; Value2: 50V; TaMin_C: -55; TaMax_C: 125
C34 = GRM188R71A225KE15D: as C1 on sheet ISE4010_MSP430
C35 = UMK107AB7105KA-T: CAP, CERM, 1uF, 50V, +/-10%, X7R, 0603; Manufacturer: Taiyo Yuden; Polarized: N; CompType: Capacitor; U/M: EA; Cap_F: 0.000001; Tolerance_%: 10; Value1: Unknown; VDC_V: 50; TaMin_C: -55; TaMax_C: 125
C36 = GRM033R71A103KA01D: CAP, CERM, 0.01uF, 10V, +/-10%, X7R, 0201; Manufacturer: MuRata; Polarized: N; CompType: Capacitor; U/M: EA; Cap_F: 0.00000001; Tolerance_%: 10; Value1: Unknown; TaMin_C: -55; TaMax_C: 125
D4 = NSR0240V2T1G: Diode, Schottky, 40V, 0.25A, SOD-523; Manufacturer: ON Semiconductor; U/M: EA; Vf_V: 0.7; Value2: 0.7V; Io_A: 0.25; Vr_V: 40; TJmax_C: 150; RJC_CperW: 600
J5 = TSW-104-07-G-D: Header, 100mil, 4x2, Gold, TH; Manufacturer: Samtec; SymbolCreator: a0411947; U/M: EA
L4 = VLF252015MT-100M: Inductor, Shielded, Ferrite, 10uH, 0.47A, 0.24 ohm, SMD; Manufacturer: TDK; Ind_H: 10.0E-6; Imax_A: 0.47; Irms: 0.94A @ 40C rise; Isat: 0.47A @ 30% inductance drop; DCR_ohm: 0.24
L5 = BLM18SG331TN1D: as L1 on sheet ISE4010_MSP430
R7 R30 = CRCW04020000Z0ED: RES, 0, 5%, 0.063 W, 0402; Manufacturer: Vishay-Dale; CompType: Resistor; Value: 0; Value_Code: 0000; Tolerance_%: 5; Power_W: 0.063; Value2: 0.063W; VDC_V: 50; TempCo: 200 ppm/C; EIA_Code: E24; U/M: EA
R11 R12 = CRCW040238K3FKED: RES, 38.3 k, 1%, 0.063 W, 0402; Manufacturer: Vishay-Dale; CompType: Resistor; Value: 38.3k; Res_ohm: 38300; Value_Code: 38k3; Tolerance_%: 1; Power_W: 0.063; Value2: 0.063W; VDC_V: 50; TempCo: 100 ppm/C; EIA_Code: E96; U/M: EA
R25 = CRCW04020000Z0ED: as R1 on sheet ISE4010_MSP430
R26 = CRCW040210K0FKED: RES, 10.0k ohm, 1%, 0.063W, 0402; Manufacturer: Vishay-Dale; CompType: Resistor; Res_ohm: 10000; Value_Code: 10k0; Tolerance_%: 1; Power_W: 0.063; VDC_V: 50; TempCo: 100 ppm/C; EIA_Code: E96; U/M: EA
R31 R34 R35 R38 R39 R42 R43 R46 = CRCW25120000Z0EG: RES, 0 ohm, 5%, 1W, 2512; Manufacturer: Vishay-Dale; CompType: Resistor; Value_Code: 0000; Tolerance_%: 5; Power_W: 1; TempCo: ppm/C; EIA_Code: E24; U/M: EA
SH-J4 SH-J5 = 2SN-BK-G: as SH-J1 on sheet ISE4010_MSP430
U4 = EA DOGM128W-6: Module, 128x64-pixel graphics display; Manufacturer: Electronic Assembly; SymbolCreator: a0799628
U7 = FDC1004DSC: 4-Channel Capacitance-to-Digital Converter for Capacitive Sensing Solutions, DSC0010B; Alternate Manufacturer: None; Manufacturer: Texas Instruments; SymbolCreator: x0208325; CompType: IC; U/M: EA
U12 = LM3630ATME: LM3630A High-Efficiency Dual-String White LED Driver, YFQ0012AKAR; Alternate Manufacturer: None; Manufacturer: Texas Instruments; SymbolCreator: a0411947; CompType: IC; U/M: EA
U13 = TMP112AIDRL: High-Accuracy, Low-Power, Digital Temperature Sensor With SMBus(TM)/Two-Wire Serial Interface, DRL0006A; Alternate Manufacturer: None; Manufacturer: Texas Instruments; SymbolCreator: a0799628; CompType: IC; U/M: EA

## Sheet ISE4010_TID_Hardware.SchDoc
size 431 x 279 mm; Date: Not shown in title block; ApprovedBy: Not shown in title block; CheckedBy: Not shown in title block; Author: Not shown in title block; CompanyName: Not shown in title block; Engineer: Not shown in title block; Organization: Not shown in title block; Address1: Not shown in title block; Address2: Not shown in title block; Address3: Not shown in title block; Address4: Not shown in title block; DocumentNumber: 1; Revision: Use project parameter SCH_Rev; SheetNumber: 1; SheetTotal: 1; PageSetup: Record=PageOptions¦CenterHorizontal=True¦CenterVertical=True¦PrintScale=1.00¦XCorrection=1.00¦YCorrection=1.00¦PrintKind=0¦BorderSize=5000000¦LeftOffset=0¦BottomOffset=0¦Orientation=2¦PaperLength=1000¦PaperWidth=1000¦Scale=100¦PaperSource=15¦PrintQuality=600¦MediaType=1¦DitherType=10¦PaperKind=Letter¦PrintScaleMode=1
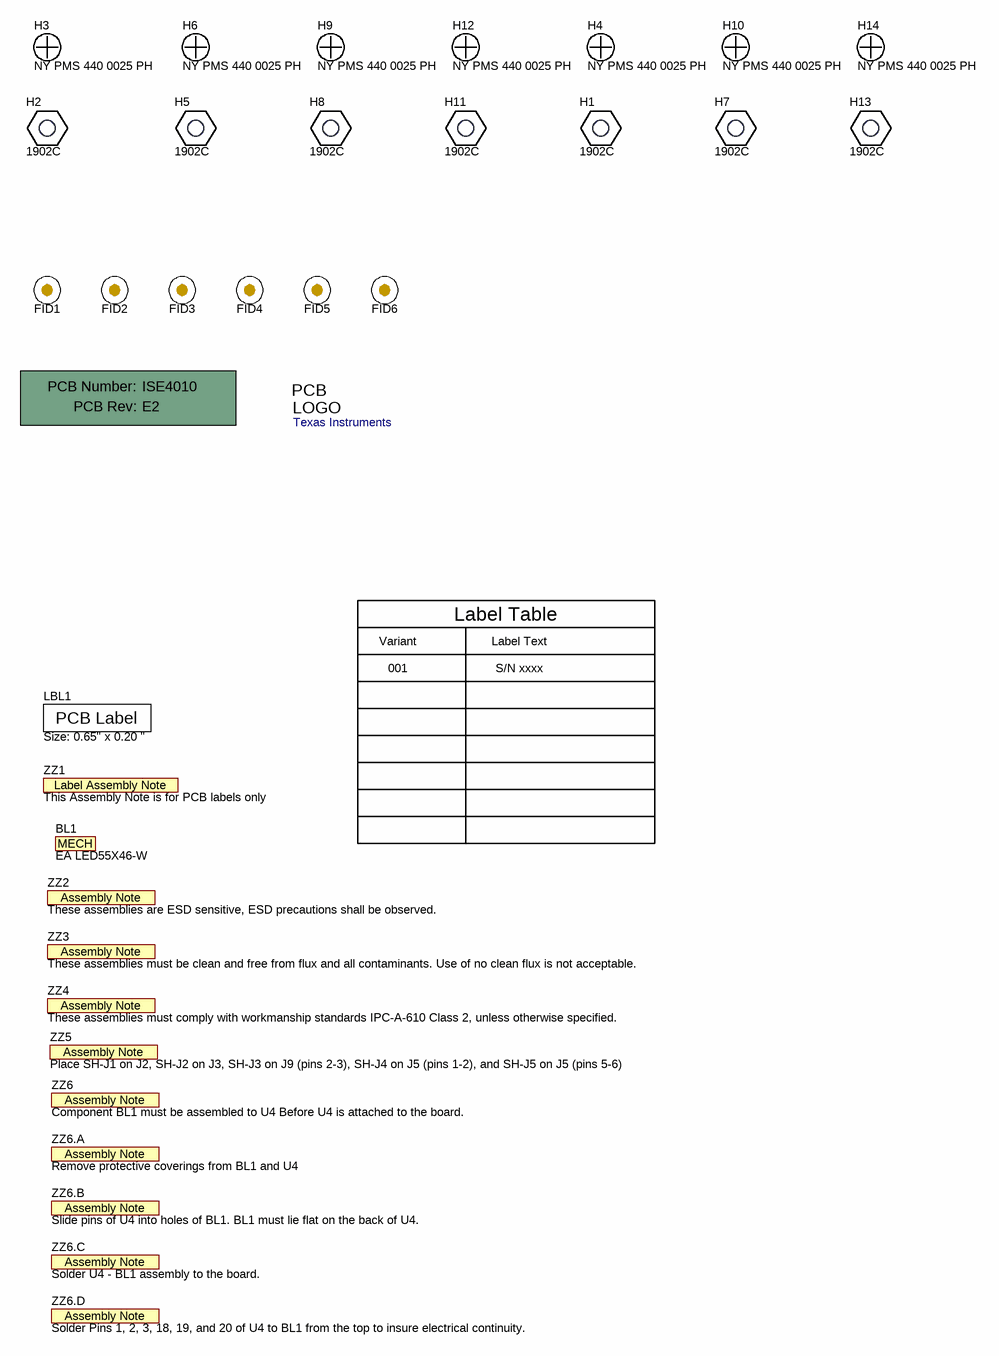
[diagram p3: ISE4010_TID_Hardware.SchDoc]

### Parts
!PCB1  Printed Circuit Board  (value not drawn)  (mechanical)
BL1  EA LED55X46-W  (mechanical)
FID1  Fiducial  [Fiducial10-20]  (value not drawn)
FID2  Fiducial  [Fiducial10-20]  (value not drawn)
FID3  Fiducial  [Fiducial10-20]  (value not drawn)
FID4  Fiducial  [Fiducial10-20]  (value not drawn)
FID5  Fiducial  [Fiducial10-20]  (value not drawn)
FID6  Fiducial  [Fiducial10-20]  (value not drawn)
H1  1902C  [Keystone_1902C]
H2  1902C  [Keystone_1902C]
H3  NY PMS 440 0025 PH  [NY PMS 440 0025 PH]
H4  NY PMS 440 0025 PH  [NY PMS 440 0025 PH]
H5  1902C  [Keystone_1902C]
H6  NY PMS 440 0025 PH  [NY PMS 440 0025 PH]
H7  1902C  [Keystone_1902C]
H8  1902C  [Keystone_1902C]
H9  NY PMS 440 0025 PH  [NY PMS 440 0025 PH]
H10  NY PMS 440 0025 PH  [NY PMS 440 0025 PH]
H11  1902C  [Keystone_1902C]
H12  NY PMS 440 0025 PH  [NY PMS 440 0025 PH]
H13  1902C  [Keystone_1902C]
H14  NY PMS 440 0025 PH  [NY PMS 440 0025 PH]
LBL1  Size: 0.65" x 0.20 "  [Label_650x200]
Logo1  Texas Instruments  [TI_Stacked_Overlay_Medium]  (no BOM)
ZZ1  This Assembly Note is for PCB labels only  [AssemblyNoteLabel]  (no BOM)
ZZ2  These assemblies are ESD sensitive, ESD precautions shall be observed.  [AssemblyNote]  (no BOM)
ZZ3  These assemblies must be clean and free from flux and all contaminants. Use of no clean flux is not acceptable.  [AssemblyNote]  (no BOM)
ZZ4  These assemblies must comply with workmanship standards IPC-A-610 Class 2, unless otherwise specified.  [AssemblyNote]  (no BOM)
ZZ5  Place SH-J1 on J2, SH-J2 on J3, SH-J3 on J9 (pins 2-3), SH-J4 on J5 (pins 1-2), and SH-J5 on J5 (pins 5-6)  [AssemblyNote]  (no BOM)
ZZ6  Component BL1 must be assembled to U4 Before U4 is attached to the board.  [AssemblyNote]  (no BOM)
ZZ6.A  Remove protective coverings from BL1 and U4  [AssemblyNote]  (no BOM)
ZZ6.B  Slide pins of U4 into holes of BL1. BL1 must lie flat on the back of U4.  [AssemblyNote]  (no BOM)
ZZ6.C  Solder U4 - BL1 assembly to the board.  [AssemblyNote]  (no BOM)
ZZ6.D  Solder Pins 1, 2, 3, 18, 19, and 20 of U4 to BL1 from the top to insure electrical continuity.  [AssemblyNote]  (no BOM)

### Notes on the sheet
- Variant
- Label Table
- Label Text
- 001
- S/N xxxx

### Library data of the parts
!PCB1 = PCB: Manufacturer: Any; PartNumber: ISE4010; SymbolCreator: a0412235
BL1 = EA LED55X46-W: LED Backlight, White; Manufacturer: Electronic Assembly; SymbolCreator: codlsc
FID1-FID6 = Fiducial: Fiducial mark.  There is nothing to buy or mount.; SymbolCreator: codlsc
H1 H2 H5 H7 H8 H11 H13 = 1902C: Standoff, Hex, 0.5"L #4-40 Nylon; Manufacturer: Keystone; CompType: Hardware; SymbolCreator: a0412235
H3 H4 H6 H9 H10 H12 H14 = NY PMS 440 0025 PH: Machine Screw, Round, #4-40 x 1/4, Nylon, Philips panhead; Manufacturer: B&F Fastener Supply; CompType: Hardware; SymbolCreator: codlsc; U/M: EA
LBL1 = THT-14-423-10: Thermal Transfer Printable Labels, 0.650" W x 0.200" H - 10,000 per roll; Manufacturer: Brady; SymbolCreator: a0412235; CompType: Label
Logo1 = TI_Logo: Texas Instrument Corporate Signature; SymbolCreator: a0412235
ZZ1 = AssemblyNoteLabel: SymbolCreator: a0412235
ZZ2-ZZ6 ZZ6.A ZZ6.B ZZ6.C ZZ6.D = AssemblyNote: SymbolCreator: codlsc

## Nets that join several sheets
3V3: ISE4010_MSP430 (16 pins), ISE4010_FDC_LCD (7 pins)
GND: ISE4010_MSP430 (51 pins), ISE4010_FDC_LCD (24 pins)
A0_SCLK: ISE4010_MSP430 (R20.2 TP8.1 U3.11), ISE4010_FDC_LCD (U4.37)
A0_SIMO: ISE4010_MSP430 (R19.2 TP6.1 U3.24), ISE4010_FDC_LCD (U4.36)
B0_SCL: ISE4010_MSP430 (R2.1 TP12.1 U3.32), ISE4010_FDC_LCD (U7.9 U12.A2 U13.1)
B0_SDA: ISE4010_MSP430 (R3.1 TP11.1 U3.31), ISE4010_FDC_LCD (U7.10 U12.A1 U13.6)
BL_EN: ISE4010_MSP430 (U3.7), ISE4010_FDC_LCD (U12.B1)
BL_PWM: ISE4010_MSP430 (U3.26), ISE4010_FDC_LCD (U12.C1)
LCD_A0: ISE4010_MSP430 (U3.6), ISE4010_FDC_LCD (U4.38)
nCSB_LCD: ISE4010_MSP430 (TP9.1 U3.10), ISE4010_FDC_LCD (U4.40)
nRST_LCD: ISE4010_MSP430 (U3.5), ISE4010_FDC_LCD (U4.39)
TMP_ALERT: ISE4010_MSP430 (U3.3), ISE4010_FDC_LCD (R26.1 U13.3)

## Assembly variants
001: not fitted C2 C3 C24 C25 FID1 FID2 FID3 FID4 FID5 FID6 R13 R14 R15 R24 Y1 ZZ2 ZZ3 ZZ4 ZZ5 ZZ6 ZZ6.A ZZ6.B ZZ6.C ZZ6.D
